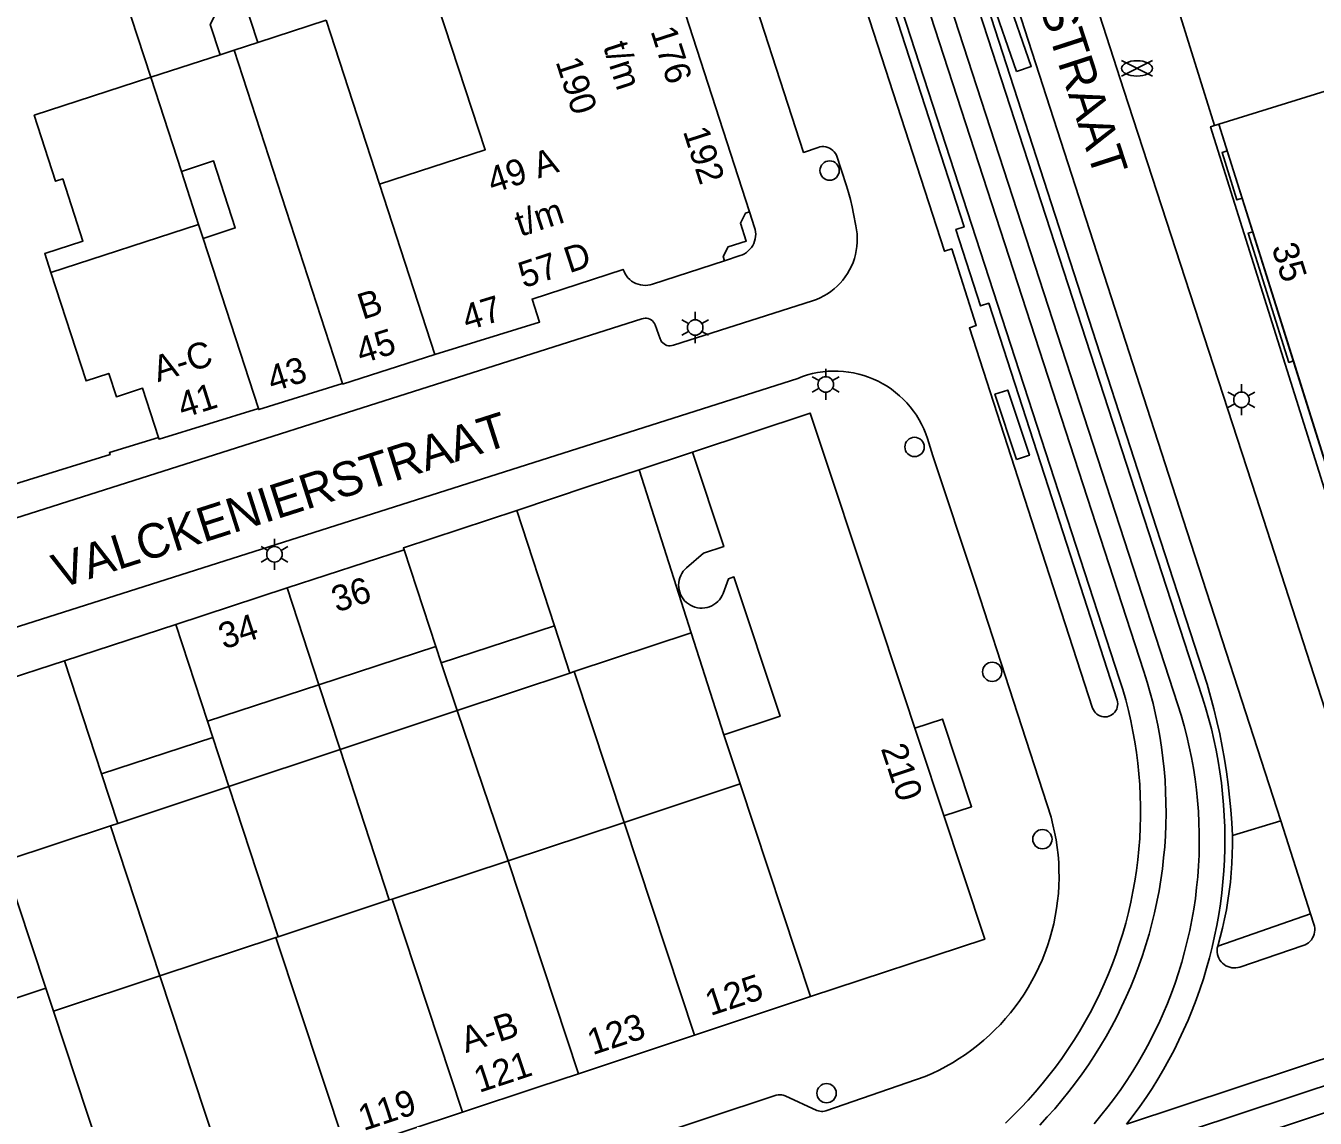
# Model space of a CAD drawing. Extents: x 122462 to 123306, y 485548 to 486417.
# Drawn here: x 122513.2 to 122587.9, y 486103.4 to 486166.7 of the extents above; entities that cross this region are included whole.
import ezdxf

# ---------------------------------------------------------------- set-up
doc = ezdxf.new("R2010")
doc.units = 0
for name, color, linetype in [('Level 1', 7, 'Continuous'), ('Level 10', 7, 'Continuous'), ('Level 11', 7, 'Continuous'), ('Level 17', 7, 'Continuous'), ('Level 19', 7, 'Continuous'), ('Level 22', 7, 'Continuous'), ('Level 23', 7, 'Continuous'), ('Level 37', 7, 'Continuous'), ('Level 4', 7, 'Continuous'), ('Level 44', 7, 'Continuous'), ('Level 5', 7, 'Continuous'), ('Level 50', 7, 'Continuous'), ('Level 52', 7, 'Continuous'), ('Level 53', 7, 'Continuous'), ('Level 58', 7, 'Continuous'), ('Level 59', 7, 'Continuous')]:
    doc.layers.add(name, color=color, linetype=linetype)

msp = doc.modelspace()

# ---------------------------------------------------------------- linework, layer by layer
at = {"layer": 'Level 1'}
for p, q in [((122520.453, 486163.738), (122516.571, 486175.67)), ((122533.713, 486157.542), (122530.622, 486167.041)), ((122524.464, 486165.044), (122520.453, 486163.738)), ((122520.453, 486163.738), (122522.227, 486158.284)), ((122582.832, 486159.479), (122582.347, 486161.021)), ((122583.699, 486156.722), (122582.832, 486159.479)), ((122584.308, 486154.786), (122583.699, 486156.722)), ((122523.223, 486155.2), (122514.664, 486152.414)), ((122523.484, 486154.399), (122523.223, 486155.2)), ((122586.662, 486147.297), (122584.308, 486154.786)), ((122541.66, 486138.63), (122543.847, 486131.945)), ((122528.36, 486134.14), (122535.127, 486136.353)), ((122521.908, 486132.032), (122528.36, 486134.14)), ((122515.449, 486129.92), (122521.908, 486132.032)), ((122543.847, 486131.945), (122537.277, 486129.797)), ((122536.96, 486130.746), (122530.194, 486128.534)), ((122537.277, 486129.797), (122536.96, 486130.746)), ((122517.595, 486123.363), (122515.449, 486129.92)), ((122530.194, 486128.534), (122523.741, 486126.425)), ((122523.741, 486126.425), (122524.052, 486125.474)), ((122553.665, 486125.632), (122554.608, 486122.781)), ((122524.052, 486125.474), (122517.595, 486123.363)), ((122554.608, 486122.781), (122547.883, 486120.557)), ((122547.883, 486120.557), (122541.157, 486118.334)), ((122541.157, 486118.334), (122534.432, 486116.111)), ((122534.273, 486116.058), (122527.827, 486113.927)), ((122534.432, 486116.111), (122534.273, 486116.058)), ((122527.706, 486113.887), (122520.981, 486111.664)), ((122527.827, 486113.927), (122527.706, 486113.887)), ((122520.981, 486111.664), (122514.806, 486109.622)), ((122514.37, 486110.938), (122508.193, 486108.896)), ((122514.806, 486109.622), (122514.37, 486110.938)), ((122551.96, 486108.225), (122558.679, 486110.459)), ((122545.239, 486105.989), (122551.96, 486108.225)), ((122531.788, 486101.542), (122538.514, 486103.763))]:
    msp.add_line(p, q, dxfattribs=at)
for points in [[(122582.347, 486161.021), (122582.09, 486160.939), (122573.029, 486189.988)], [(122536.727, 486169.039), (122539.836, 486159.534), (122533.713, 486157.542)], [(122525.613, 486168.937), (122524.866, 486168.694), (122523.896, 486166.789), (122524.464, 486165.044)], [(122536.92, 486147.679), (122542.986, 486149.55), (122542.551, 486150.88), (122547.824, 486152.605), (122547.875, 486152.473), (122547.939, 486152.347), (122548.016, 486152.228), (122548.105, 486152.119), (122548.205, 486152.019), (122548.315, 486151.93), (122548.434, 486151.853), (122548.56, 486151.789), (122548.692, 486151.739), (122548.829, 486151.702), (122548.969, 486151.681), (122549.11, 486151.674), (122549.251, 486151.681), (122549.391, 486151.704), (122549.527, 486151.741), (122553.696, 486153.104), (122553.618, 486153.343), (122553.907, 486153.906), (122554.954, 486154.248), (122554.616, 486155.285), (122554.915, 486155.865), (122555.152, 486155.942), (122551.447, 486167.4)], [(122514.664, 486152.414), (122514.306, 486153.516), (122516.52, 486154.236), (122515.345, 486157.847), (122514.938, 486157.715), (122513.694, 486161.539), (122520.453, 486163.738)], [(122522.227, 486158.284), (122524.087, 486158.889), (122525.35, 486155.006), (122523.484, 486154.399)], [(122531.561, 486145.991), (122531.57, 486145.959), (122536.92, 486147.679)], [(122590.431, 486135.31), (122588.712, 486140.776), (122586.662, 486147.297)], [(122526.69, 486144.548), (122526.709, 486144.479), (122531.561, 486145.991)], [(122520.902, 486142.855), (122520.929, 486142.759), (122526.69, 486144.548)], [(122558.679, 486110.459), (122568.779, 486113.779), (122562.578, 486132.488), (122558.67, 486144.279), (122551.84, 486142.019)], [(122502.959, 486137.273), (122508.58, 486139.009), (122508.604, 486138.938), (122518.09, 486141.87), (122518.055, 486141.989), (122520.902, 486142.855)], [(122551.84, 486142.019), (122553.658, 486136.542), (122552.49, 486136.155), (122551.505, 486135.313), (122551.402, 486135.215), (122551.31, 486135.106), (122551.23, 486134.988), (122551.163, 486134.863), (122551.11, 486134.73), (122551.072, 486134.593), (122551.048, 486134.453), (122551.039, 486134.311), (122551.046, 486134.169), (122551.068, 486134.028), (122551.104, 486133.89), (122551.156, 486133.757), (122551.221, 486133.631), (122551.299, 486133.512), (122551.389, 486133.402), (122551.491, 486133.302), (122551.603, 486133.214), (122551.724, 486133.138), (122551.852, 486133.076), (122551.985, 486133.028), (122552.124, 486132.994), (122552.265, 486132.975), (122552.407, 486132.971), (122552.549, 486132.983), (122552.689, 486133.01), (122552.825, 486133.051), (122552.956, 486133.107), (122553.08, 486133.176), (122553.197, 486133.259), (122553.303, 486133.353), (122553.399, 486133.458), (122553.484, 486133.573), (122553.555, 486133.696), (122553.613, 486133.826), (122553.939, 486134.678), (122554.242, 486134.779), (122556.917, 486126.71), (122553.665, 486125.632)], [(122535.127, 486136.353), (122535.09, 486136.459), (122541.66, 486138.63)], [(122538.514, 486103.763), (122542.929, 486105.219), (122545.239, 486105.989)]]:
    msp.add_lwpolyline(points, dxfattribs=at)
at = {"layer": 'Level 10'}
for points in [[(122593.88, 486122.67), (122581.87, 486160.871), (122582.347, 486161.021), (122593.17, 486126.596), (122609.476, 486131.683), (122610.508, 486128.398), (122636.017, 486136.87), (122635.639, 486138.009), (122641.442, 486139.936), (122641.82, 486138.797), (122654.062, 486142.863), (122653.684, 486144.002), (122661.008, 486146.434), (122661.386, 486145.295), (122666.224, 486146.902)], [(122553.696, 486153.104), (122553.618, 486153.343), (122553.907, 486153.906), (122554.954, 486154.248), (122554.616, 486155.285), (122554.915, 486155.865), (122555.152, 486155.942), (122555.444, 486155.039), (122555.479, 486154.908), (122555.5, 486154.774), (122555.507, 486154.638), (122555.5, 486154.502), (122555.479, 486154.368), (122555.444, 486154.237), (122555.395, 486154.11), (122555.333, 486153.989), (122555.259, 486153.875), (122555.174, 486153.77), (122555.078, 486153.673), (122554.973, 486153.588), (122554.859, 486153.514), (122554.738, 486153.452), (122554.611, 486153.403), (122553.696, 486153.104)]]:
    msp.add_lwpolyline(points, dxfattribs=at)
at = {"layer": 'Level 11'}
msp.add_lwpolyline([(122564.728, 486126.008), (122566.338, 486126.542), (122568.021, 486121.465), (122566.411, 486120.931)], dxfattribs=at)
at = {"layer": 'Level 17'}
for p, q in [((122515.449, 486129.92), (122508.799, 486127.749)), ((122585.928, 486120.64), (122583.131, 486119.791)), ((122585.928, 486120.64), (122587.665, 486115.264)), ((122587.665, 486115.264), (122582.281, 486113.381))]:
    msp.add_line(p, q, dxfattribs=at)
for points in [[(122590.174, 486121.943), (122584.499, 486139.44), (122576.84, 486162.998), (122570.999, 486181.078), (122570.636, 486182.152), (122570.261, 486183.222), (122569.874, 486184.288), (122569.474, 486185.35), (122569.063, 486186.406), (122568.64, 486187.459), (122568.205, 486188.506), (122567.839, 486189.363), (122567.464, 486190.216), (122567.082, 486191.066), (122554.438, 486218.823), (122554.337, 486219.064)], [(122563.721, 486183.981), (122578.731, 486137.611), (122581.661, 486128.561), (122581.867, 486127.847), (122582.058, 486127.129), (122582.234, 486126.407), (122582.395, 486125.682), (122582.541, 486124.954), (122582.672, 486124.222), (122582.787, 486123.488), (122582.886, 486122.752), (122582.971, 486122.014), (122583.04, 486121.274), (122583.093, 486120.533), (122583.131, 486119.791)], [(122550.587, 486183.123), (122558.276, 486159.379), (122559.118, 486159.673), (122559.229, 486159.702), (122559.342, 486159.717), (122559.457, 486159.717), (122559.57, 486159.701), (122559.681, 486159.671), (122559.786, 486159.627), (122559.885, 486159.569), (122559.976, 486159.498), (122560.056, 486159.417), (122560.125, 486159.325), (122560.181, 486159.226), (122560.758, 486157.452), (122560.884, 486157.051), (122560.994, 486156.646), (122561.09, 486156.238), (122561.169, 486155.825), (122561.311, 486155.129), (122561.353, 486154.894), (122561.38, 486154.656), (122561.392, 486154.417), (122561.388, 486154.177), (122561.37, 486153.939), (122561.336, 486153.701), (122561.287, 486153.467), (122561.223, 486153.236), (122561.145, 486153.01), (122561.053, 486152.789), (122560.946, 486152.575), (122560.826, 486152.367), (122560.694, 486152.168), (122560.548, 486151.978), (122560.391, 486151.797), (122560.223, 486151.627), (122560.045, 486151.467), (122559.856, 486151.32), (122559.659, 486151.184), (122559.453, 486151.062), (122559.24, 486150.953), (122559.02, 486150.857), (122558.795, 486150.776), (122550.741, 486148.21), (122550.649, 486148.185), (122550.554, 486148.174), (122550.458, 486148.178), (122550.365, 486148.198), (122550.275, 486148.232), (122550.192, 486148.28), (122550.118, 486148.341), (122550.055, 486148.412), (122550.003, 486148.493), (122549.965, 486148.581), (122549.677, 486149.381), (122549.639, 486149.467), (122549.588, 486149.546), (122549.524, 486149.616), (122549.45, 486149.675), (122549.368, 486149.721), (122549.28, 486149.753), (122549.187, 486149.771), (122549.093, 486149.774), (122548.999, 486149.761), (122548.909, 486149.734), (122508.333, 486136.828)], [(122575.767, 486126.669), (122575.662, 486126.673), (122575.558, 486126.691), (122575.458, 486126.723), (122575.363, 486126.769), (122575.276, 486126.829), (122575.198, 486126.899), (122575.13, 486126.981), (122575.075, 486127.07), (122575.033, 486127.167), (122572.308, 486135.574), (122567.887, 486149.212), (122568.291, 486149.343), (122566.865, 486153.789), (122566.447, 486153.653), (122557.301, 486181.861)], [(122558.761, 486182.321), (122567.578, 486155.067), (122567.112, 486154.916), (122568.542, 486150.49), (122569.01, 486150.641), (122573.739, 486136.028), (122576.453, 486127.639), (122576.477, 486127.536), (122576.487, 486127.431), (122576.481, 486127.326), (122576.461, 486127.223), (122576.427, 486127.123), (122576.378, 486127.029), (122576.318, 486126.943), (122576.245, 486126.866), (122576.163, 486126.801), (122576.072, 486126.747), (122575.974, 486126.707), (122575.872, 486126.681), (122575.767, 486126.669)], [(122585.928, 486120.64), (122580.285, 486138.104), (122567.151, 486178.751)], [(122583.699, 486156.722), (122583.393, 486156.627), (122582.536, 486159.387), (122582.832, 486159.479)], [(122586.662, 486147.297), (122586.402, 486147.215), (122584.051, 486154.705), (122584.308, 486154.786)], [(122501.77, 486128.417), (122557.938, 486146.289), (122558.219, 486146.396), (122558.505, 486146.487), (122558.795, 486146.563), (122559.09, 486146.624), (122559.387, 486146.668), (122559.686, 486146.697), (122559.986, 486146.71), (122560.286, 486146.708), (122560.586, 486146.689), (122560.885, 486146.654), (122561.181, 486146.604), (122561.474, 486146.537), (122561.763, 486146.456), (122562.047, 486146.359), (122562.326, 486146.247), (122562.599, 486146.121), (122562.864, 486145.98), (122563.122, 486145.826), (122563.371, 486145.658), (122563.61, 486145.477), (122563.84, 486145.283), (122564.06, 486145.078), (122564.268, 486144.861), (122564.464, 486144.634), (122564.648, 486144.396), (122564.819, 486144.149), (122564.976, 486143.893), (122565.12, 486143.63)], [(122565.12, 486143.63), (122565.25, 486143.359), (122565.365, 486143.081), (122565.466, 486142.798), (122565.779, 486141.805), (122568.271, 486134.294), (122572.619, 486120.852), (122572.732, 486120.421), (122572.829, 486119.987), (122572.911, 486119.549), (122572.977, 486119.108), (122573.028, 486118.666), (122573.063, 486118.222), (122573.082, 486117.777), (122573.085, 486117.332), (122573.073, 486116.886), (122573.045, 486116.442), (122573.001, 486115.999), (122572.942, 486115.557), (122572.867, 486115.118), (122572.777, 486114.682), (122572.671, 486114.25), (122572.55, 486113.821), (122572.414, 486113.397), (122572.263, 486112.978), (122572.097, 486112.565), (122571.916, 486112.158), (122571.722, 486111.757), (122571.513, 486111.364), (122571.291, 486110.978), (122571.055, 486110.6), (122570.805, 486110.231), (122570.543, 486109.871), (122570.269, 486109.52), (122569.982, 486109.18), (122569.683, 486108.849), (122569.373, 486108.53), (122569.051, 486108.222), (122568.719, 486107.925), (122568.377, 486107.64), (122568.025, 486107.368), (122567.663, 486107.108), (122567.292, 486106.861), (122566.913, 486106.627), (122566.526, 486106.407), (122566.131, 486106.201), (122565.729, 486106.009), (122565.321, 486105.831), (122559.577, 486103.839), (122559.491, 486103.816), (122559.403, 486103.803), (122559.314, 486103.802), (122559.226, 486103.812), (122559.139, 486103.832), (122559.056, 486103.864), (122557.204, 486104.711), (122557.107, 486104.747), (122557.006, 486104.768), (122556.902, 486104.774), (122556.799, 486104.764), (122556.699, 486104.74), (122516.8, 486091.515)], [(122583.131, 486119.791), (122583.135, 486119.25), (122583.125, 486118.709), (122583.102, 486118.169), (122583.065, 486117.629), (122583.014, 486117.091), (122582.95, 486116.554), (122582.872, 486116.018), (122582.78, 486115.485), (122582.675, 486114.955), (122582.557, 486114.427), (122582.426, 486113.902), (122582.281, 486113.381)], [(122587.665, 486115.264), (122587.859, 486114.664), (122587.889, 486114.548), (122587.905, 486114.43), (122587.907, 486114.31), (122587.894, 486114.191), (122587.867, 486114.074), (122587.826, 486113.962), (122587.773, 486113.855), (122587.706, 486113.755), (122587.629, 486113.664), (122587.541, 486113.583), (122587.444, 486113.513), (122587.339, 486113.455), (122587.228, 486113.41), (122583.567, 486112.172), (122583.451, 486112.141), (122583.332, 486112.123), (122583.212, 486112.12), (122583.093, 486112.131), (122582.976, 486112.157), (122582.862, 486112.196), (122582.755, 486112.249), (122582.654, 486112.314), (122582.562, 486112.391), (122582.479, 486112.478), (122582.408, 486112.575), (122582.349, 486112.679), (122582.302, 486112.79), (122582.27, 486112.905), (122582.251, 486113.024), (122582.247, 486113.144), (122582.257, 486113.263), (122582.281, 486113.381)]]:
    msp.add_lwpolyline(points, dxfattribs=at)
at = {"layer": 'Level 19'}
for p, q in [((122523.223, 486155.2), (122522.227, 486158.284)), ((122548.752, 486140.992), (122551.774, 486131.545)), ((122544.742, 486129.206), (122543.847, 486131.945)), ((122551.774, 486131.545), (122544.995, 486129.291)), ((122553.665, 486125.632), (122551.774, 486131.545)), ((122538.212, 486127.035), (122537.277, 486129.797)), ((122544.742, 486129.206), (122538.212, 486127.035)), ((122544.995, 486129.291), (122544.742, 486129.206)), ((122547.883, 486120.557), (122544.995, 486129.291)), ((122531.422, 486124.777), (122530.194, 486128.534)), ((122538.212, 486127.035), (122531.422, 486124.777)), ((122541.157, 486118.334), (122538.212, 486127.035)), ((122524.98, 486122.635), (122524.052, 486125.474)), ((122531.422, 486124.777), (122524.98, 486122.635)), ((122534.273, 486116.058), (122531.422, 486124.777)), ((122518.534, 486120.491), (122517.595, 486123.363)), ((122524.98, 486122.635), (122518.534, 486120.491)), ((122527.827, 486113.927), (122524.98, 486122.635)), ((122518.534, 486120.491), (122518.11, 486120.35)), ((122518.11, 486120.35), (122511.943, 486118.299)), ((122520.981, 486111.664), (122518.11, 486120.35)), ((122514.37, 486110.938), (122511.943, 486118.299))]:
    msp.add_line(p, q, dxfattribs=at)
at = {"layer": 'Level 22'}
for p, q in [((122548.752, 486140.992), (122551.84, 486142.019)), ((122541.66, 486138.63), (122545.864, 486140.031))]:
    msp.add_line(p, q, dxfattribs=at)
at = {"layer": 'Level 23'}
msp.add_line((122545.864, 486140.031), (122548.752, 486140.992), dxfattribs=at)
at = {"layer": 'Level 37'}
for p, q in [((122670.91, 486132.634), (122575.077, 486100.86)), ((122671.362, 486131.258), (122572.236, 486098.337))]:
    msp.add_line(p, q, dxfattribs=at)
for points in [[(122577, 486103.056), (122577.388, 486103.563), (122577.764, 486104.08), (122578.127, 486104.605), (122578.478, 486105.139), (122578.816, 486105.681), (122579.14, 486106.231), (122579.452, 486106.789), (122579.75, 486107.354), (122580.034, 486107.926), (122580.305, 486108.504), (122580.562, 486109.089), (122580.805, 486109.68), (122581.034, 486110.276), (122581.248, 486110.878), (122581.448, 486111.485), (122581.633, 486112.096), (122581.804, 486112.711), (122581.96, 486113.331), (122582.101, 486113.954), (122582.228, 486114.58), (122582.339, 486115.209), (122582.435, 486115.84), (122582.516, 486116.474), (122582.582, 486117.109), (122582.633, 486117.746), (122582.668, 486118.384), (122582.689, 486119.022), (122582.694, 486119.661), (122582.684, 486120.3), (122582.658, 486120.938), (122582.618, 486121.575), (122582.562, 486122.212), (122582.491, 486122.846), (122582.405, 486123.479), (122582.303, 486124.11), (122582.187, 486124.738), (122582.056, 486125.363), (122581.91, 486125.985), (122581.749, 486126.603), (122581.573, 486127.217), (122581.383, 486127.827), (122563.777, 486181.956)], [(122561.115, 486181.258), (122578.002, 486129.3), (122578.193, 486128.685), (122578.37, 486128.066), (122578.531, 486127.443), (122578.677, 486126.815), (122578.807, 486126.185), (122578.922, 486125.551), (122579.021, 486124.915), (122579.105, 486124.277), (122579.172, 486123.637), (122579.225, 486122.995), (122579.261, 486122.352), (122579.281, 486121.708), (122579.286, 486121.065), (122579.275, 486120.421), (122579.248, 486119.777), (122579.206, 486119.135), (122579.147, 486118.494), (122579.073, 486117.854), (122578.984, 486117.217), (122578.878, 486116.581), (122578.757, 486115.949), (122578.621, 486115.32), (122578.469, 486114.694), (122578.302, 486114.072), (122578.12, 486113.455), (122577.922, 486112.842), (122577.71, 486112.234), (122577.482, 486111.632), (122577.24, 486111.035), (122576.984, 486110.445), (122576.713, 486109.861), (122576.428, 486109.283), (122576.128, 486108.713), (122575.815, 486108.151), (122575.488, 486107.596), (122575.148, 486107.05), (122574.794, 486106.512), (122574.427, 486105.982), (122574.047, 486105.462), (122573.655, 486104.952), (122573.25, 486104.451), (122572.833, 486103.961), (122572.404, 486103.48), (122571.964, 486103.011)], [(122562.37, 486181.499), (122579.975, 486127.368), (122580.163, 486126.765), (122580.335, 486126.158), (122580.493, 486125.547), (122580.635, 486124.932), (122580.761, 486124.313), (122580.872, 486123.692), (122580.968, 486123.068), (122581.048, 486122.442), (122581.112, 486121.814), (122581.161, 486121.184), (122581.194, 486120.554), (122581.211, 486119.923), (122581.212, 486119.292), (122581.198, 486118.661), (122581.168, 486118.03), (122581.122, 486117.401), (122581.06, 486116.772), (122580.983, 486116.146), (122580.89, 486115.521), (122580.781, 486114.9), (122580.657, 486114.281), (122580.518, 486113.665), (122580.363, 486113.053), (122580.193, 486112.445), (122580.008, 486111.842), (122579.808, 486111.243), (122579.593, 486110.649), (122579.363, 486110.061), (122579.119, 486109.479), (122578.86, 486108.904), (122578.587, 486108.335), (122578.3, 486107.773), (122577.998, 486107.218), (122577.683, 486106.671), (122577.355, 486106.132), (122577.013, 486105.601), (122576.658, 486105.079), (122576.29, 486104.566), (122575.909, 486104.063), (122575.516, 486103.569), (122575.111, 486103.085)], [(122569.977, 486103.129), (122570.426, 486103.561), (122570.864, 486104.003), (122571.291, 486104.457), (122571.706, 486104.921), (122572.11, 486105.395), (122572.501, 486105.88), (122572.88, 486106.374), (122573.247, 486106.877), (122573.601, 486107.39), (122573.941, 486107.911), (122574.269, 486108.44), (122574.583, 486108.978), (122574.884, 486109.524), (122575.17, 486110.077), (122575.443, 486110.636), (122575.701, 486111.203), (122575.946, 486111.776), (122576.175, 486112.355), (122576.39, 486112.939), (122576.591, 486113.529), (122576.776, 486114.123), (122576.946, 486114.723), (122577.101, 486115.326), (122577.241, 486115.932), (122577.366, 486116.543), (122577.475, 486117.156), (122577.569, 486117.771), (122577.648, 486118.389), (122577.71, 486119.009), (122577.757, 486119.63), (122577.789, 486120.252), (122577.805, 486120.874), (122577.805, 486121.497), (122577.79, 486122.12), (122577.758, 486122.742), (122577.712, 486123.363), (122577.649, 486123.982), (122577.571, 486124.6), (122577.478, 486125.216), (122577.369, 486125.829), (122577.245, 486126.439), (122577.105, 486127.046), (122576.95, 486127.649), (122576.78, 486128.248), (122576.595, 486128.843), (122559.708, 486180.8)], [(122577, 486103.056), (122670.449, 486134.039)]]:
    msp.add_lwpolyline(points, dxfattribs=at)
at = {"layer": 'Level 4'}
for p, q in [((122525.613, 486168.937), (122526.649, 486165.755)), ((122598.733, 486166.119), (122582.347, 486161.021)), ((122525.275, 486165.308), (122524.464, 486165.044)), ((122526.649, 486165.755), (122525.275, 486165.308)), ((122531.561, 486145.991), (122525.275, 486165.308)), ((122536.92, 486147.679), (122533.713, 486157.542)), ((122526.69, 486144.548), (122523.484, 486154.399)), ((122536.96, 486130.746), (122535.127, 486136.353)), ((122530.194, 486128.534), (122528.36, 486134.14)), ((122523.741, 486126.425), (122521.908, 486132.032)), ((122558.679, 486110.459), (122554.608, 486122.781)), ((122551.96, 486108.225), (122547.883, 486120.557)), ((122545.239, 486105.989), (122541.157, 486118.334)), ((122538.514, 486103.763), (122534.432, 486116.111)), ((122531.788, 486101.542), (122527.706, 486113.887)), ((122525.059, 486099.319), (122520.981, 486111.664)), ((122518.881, 486097.291), (122514.806, 486109.622))]:
    msp.add_line(p, q, dxfattribs=at)
msp.add_lwpolyline([(122520.902, 486142.855), (122519.973, 486145.712), (122518.455, 486145.218), (122518.015, 486146.57), (122516.704, 486146.144), (122514.664, 486152.414)], dxfattribs=at)
at = {"layer": 'Level 44'}
for points in [[(122570.621, 486164.069), (122569.141, 486168.379), (122569.991, 486168.671), (122571.471, 486164.361), (122570.621, 486164.069)], [(122570.615, 486141.587), (122569.364, 486145.371), (122570.114, 486145.613), (122571.365, 486141.829), (122570.615, 486141.587)]]:
    msp.add_lwpolyline(points, dxfattribs=at)
at = {"layer": 'Level 5'}
msp.add_line((122530.622, 486167.041), (122526.649, 486165.755), dxfattribs=at)
at = {"layer": 'Level 50'}
for p, q in [((122551.611, 486149.461), (122551.221, 486149.686)), ((122552.001, 486149.686), (122552.001, 486150.136)), ((122552.78, 486149.686), (122552.39, 486149.461)), ((122551.611, 486149.011), (122551.221, 486148.786)), ((122552.78, 486148.786), (122552.39, 486149.011)), ((122552.001, 486148.336), (122552.001, 486148.786)), ((122559.564, 486146.385), (122559.564, 486146.835)), ((122559.174, 486146.16), (122558.784, 486146.385)), ((122560.343, 486146.385), (122559.953, 486146.16)), ((122583.655, 486145.496), (122583.655, 486145.946)), ((122559.174, 486145.71), (122558.784, 486145.485)), ((122559.564, 486145.035), (122559.564, 486145.485)), ((122560.343, 486145.485), (122559.953, 486145.71)), ((122583.265, 486145.271), (122582.875, 486145.496)), ((122584.434, 486145.496), (122584.044, 486145.271)), ((122583.265, 486144.821), (122582.875, 486144.596)), ((122583.655, 486144.146), (122583.655, 486144.596)), ((122584.434, 486144.596), (122584.044, 486144.821)), ((122527.619, 486136.54), (122527.619, 486136.99)), ((122527.229, 486136.315), (122526.839, 486136.54)), ((122528.398, 486136.54), (122528.008, 486136.315)), ((122527.229, 486135.865), (122526.839, 486135.64)), ((122527.619, 486135.19), (122527.619, 486135.64)), ((122528.398, 486135.64), (122528.008, 486135.865))]:
    msp.add_line(p, q, dxfattribs=at)
for centre in [(122552.001, 486149.236), (122559.564, 486145.935), (122583.655, 486145.046), (122527.619, 486136.09)]:
    msp.add_circle(centre, 0.45, dxfattribs=at)
at = {"layer": 'Level 52'}
for p, q in [((122576.711, 486163.81), (122578.492, 486164.7)), ((122576.711, 486164.7), (122578.492, 486163.81))]:
    msp.add_line(p, q, dxfattribs=at)
msp.add_ellipse((122577.601, 486164.253), major_axis=(0.89, 0), ratio=0.5, dxfattribs=at)
at = {"layer": 'Level 53'}
for centre in [(122559.791, 486158.331), (122564.711, 486142.311), (122569.211, 486129.281), (122572.121, 486119.581), (122559.611, 486104.861)]:
    msp.add_circle(centre, 0.56, dxfattribs=at)

# ---------------------------------------------------------------- texts
at = {"layer": 'Level 58'}
for s, rotation, p in [('176', 287.92298, (122549.4, 486166.419)), ('t/m', 287.92298, (122546.65, 486165.532)), ('190', 287.92298, (122543.9, 486164.642)), ('192', 287.94171, (122551.278, 486160.608)), ('49 A', 18.12483, (122540.256, 486156.999)), ('t/m', 18.12483, (122541.865, 486154.485)), ('57 D', 18.12483, (122542.054, 486151.506)), ('35', 287.45195, (122585.39, 486153.879)), ('B', 17.52161, (122532.727, 486149.68)), ('47', 17.08866, (122538.776, 486149.039)), ('45', 17.52161, (122532.641, 486147.116)), ('A-C', 17.52161, (122520.861, 486146.058)), ('43', 17.52161, (122527.491, 486145.489)), ('41', 17.52161, (122522.296, 486143.964)), ('36', 18.09833, (122531.224, 486132.711)), ('34', 18.07996, (122524.677, 486130.571)), ('210', 288.34319, (122562.746, 486124.839)), ('125', 18.23833, (122552.883, 486109.327)), ('A-B', 18.23833, (122538.715, 486107.178)), ('123', 18.23833, (122546.052, 486107.056)), ('121', 18.23833, (122539.478, 486104.872)), ('119', 18.23833, (122532.78, 486102.661))]:
    msp.add_text(s, height=1.5, rotation=rotation, dxfattribs=at).set_placement(p)
at = {"layer": 'Level 59'}
for s, rotation, p in [('ROETERSSTRAAT', 287.96929, (122567.953, 486180.157)), ('VALCKENIERSTRAAT', 17.74641, (122515.153, 486134.089))]:
    msp.add_text(s, height=2, rotation=rotation, dxfattribs=at).set_placement(p)

doc.saveas('drawing.dxf')
